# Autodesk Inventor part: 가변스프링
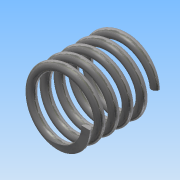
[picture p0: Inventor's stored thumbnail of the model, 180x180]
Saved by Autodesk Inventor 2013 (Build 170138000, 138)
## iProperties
Created: 2014-12
Part Number: 가변스프링
Material: 강철, 탄소
Document SubType Name: Modeling
Designer: Administrator
Density: 7.87 g/cm^3
Mass: 18.7382 g
Surface Area: 32.4003 cm^2
Volume: 2.38096 cm^3
Author: Administrator
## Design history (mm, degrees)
sketch "스케치1"
  geometry: L1 (0, 0)-(0, 25.208); L2 (0, 25.208)-(11, 25.208); L3 (0, 0)-(11, 0); C1 r 1.5 at (11, 0)
  constraints: 6 end point, 2 parallel, 1 centre point, 1 coincident, 1 perpendicular, 1 vertical
  dimensions: "d0" = 25.20829 distance of L1.start L1.end (derived); "d1" = 11 distance of L1.end L2.end; "d2" = 3 diameter of C1
feature "코일1" sketch "스케치1" pitch "d3" = 10; turns "d5" = 5; dims "d4" = 25.20829 (= d0), "d6" = 0, angle "d7" = 90 deg, angle "d8" = 90 deg, "d9" = 0, "d10" = 0
sketch "스케치2"
  geometry: L1 (25.208, 16.5)-(0, 16.5); L2 (0, 16.5)-(0, -16.5); L3 (0, -16.5)-(25.208, -16.5); L4 (25.208, -16.5)-(25.208, 16.5); 2 further points
  constraints: 8 end point, 2 coincident, 2 parallel, 1 horizontal, 1 midpoint, 1 perpendicular
  dimensions: "d11" = 25.20829 distance of L2.end L3.end (derived); "d13" = 33 distance of L3.end L1.start
extrude "돌출1" sketch "스케치2" stored distance "d14" = 0; taper "d15" = 0 deg
node "솔리드1"
